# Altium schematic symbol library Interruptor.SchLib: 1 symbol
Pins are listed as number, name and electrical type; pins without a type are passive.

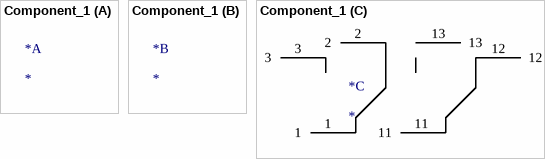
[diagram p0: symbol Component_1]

## Component_1
designator *
footprint SLW-1678105-6A-N-D (Interruptor)
part C pins: 1, 2, 3, 11, 12, 13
